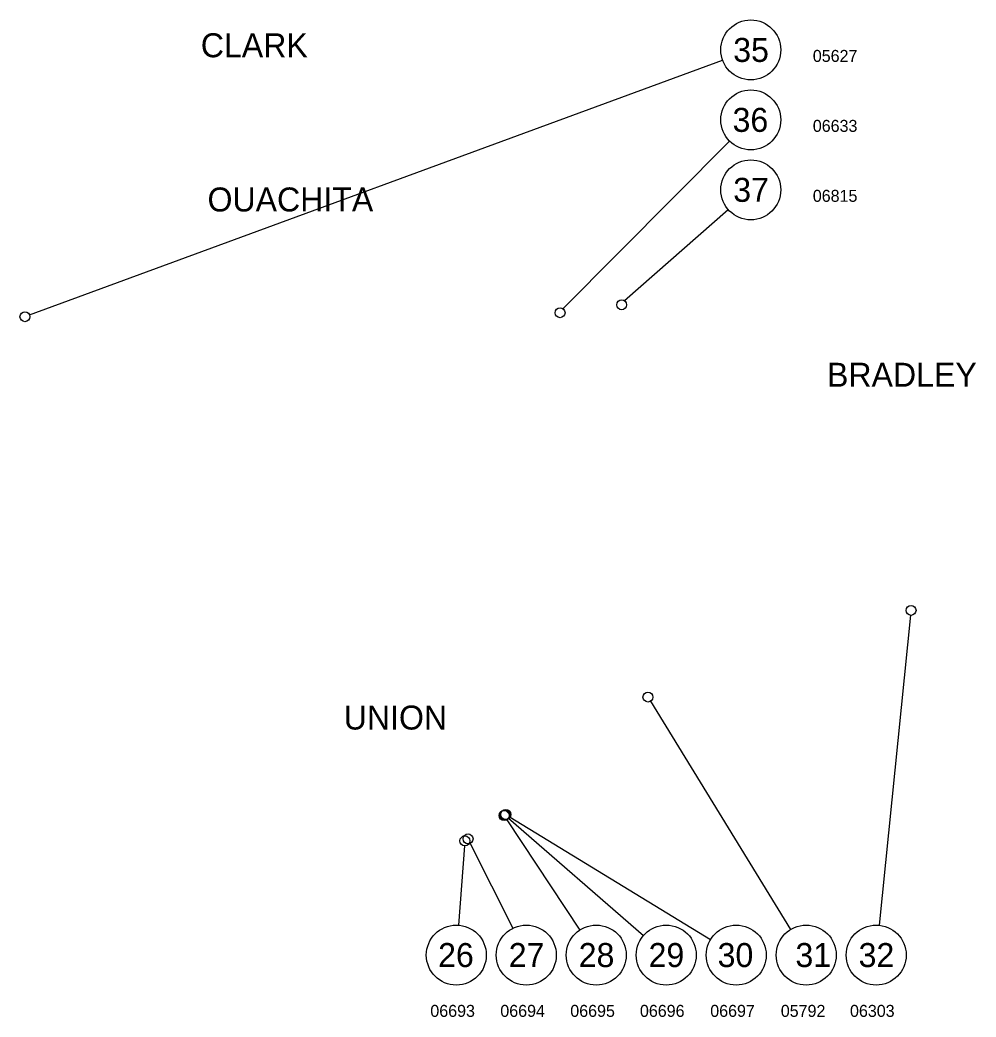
# Model space of a CAD drawing. Extents: x -43543 to 34500, y -13675 to 11152.
# Drawn here: x 24936 to 34500, y -7846 to 2131 of the extents above; entities that cross this region are included whole.
import ezdxf

# ---------------------------------------------------------------- set-up
doc = ezdxf.new("R2010")
doc.units = 0
for name, color, linetype in [('2', 7, 'Continuous'), ('R_Annotation', 7, 'Continuous'), ('R_No Plot', 7, 'Continuous')]:
    doc.layers.add(name, color=color, linetype=linetype)

msp = doc.modelspace()

# ---------------------------------------------------------------- linework, layer by layer
at = {"layer": 'R_Annotation'}
for p, q in [((25032.6, -820.5), (31965, 1728)), ((30367.8, -757.6), (32035, 918.8)), ((30983.5, -677.2), (32021.1, 233.6)), ((33844.7, -3825.8), (33531, -6926.7)), ((31244.4, -4686.3), (32644.1, -6969.5)), ((29806.6, -5871.5), (30535.5, -6974.9)), ((29824.3, -5857.1), (31174.3, -7028.6)), ((29838.3, -5845), (31844.7, -7069)), ((29382.9, -6133.1), (29323.3, -6926.1)), ((29440.3, -6107.4), (29866.4, -6957.1))]:
    msp.add_line(p, q, dxfattribs=at)
for centre, radius in [((32246.6, 1831.5), 300), ((32246.6, 1131.5), 300), ((32246.6, 431.5), 300), ((30954.9, -718.2), 50), ((24985.7, -837.8), 50), ((30338.4, -798.1), 50), ((33849.7, -3776), 50), ((31218.3, -4643.7), 50), ((29779.1, -5829.8), 50), ((29786.5, -5824.4), 50), ((29795.6, -5819), 50), ((29386.6, -6083.2), 50), ((29417.9, -6062.7), 50), ((29300.9, -7225.2), 300), ((30000.9, -7225.2), 300), ((30700.9, -7225.2), 300), ((31400.9, -7225.2), 300), ((32100.9, -7225.2), 300), ((32800.9, -7225.2), 300), ((33500.9, -7225.2), 300)]:
    msp.add_circle(centre, radius, dxfattribs=at)

# ---------------------------------------------------------------- texts
at = {"layer": '2'}
for s, p in [('CLARK', (26744.8, 1758.1)), ('OUACHITA', (26812, 215)), ('BRADLEY', (33008.8, -1538.7)), ('UNION', (28174.4, -4968.7))]:
    msp.add_text(s, height=240, dxfattribs=at).set_placement(p)
at = {"layer": 'R_Annotation'}
for s, p in [('35', (32070.8, 1711.5)), ('36', (32064.2, 1011.5)), ('37', (32070.8, 311.5)), ('26', (29118.5, -7345.2)), ('27', (29825.1, -7345.2)), ('28', (30525.1, -7345.2)), ('29', (31224.2, -7345.2)), ('30', (31914.7, -7345.2)), ('31', (32693.1, -7345.2)), ('32', (33325.1, -7345.2))]:
    msp.add_text(s, height=240, dxfattribs=at).set_placement(p)
at = {"layer": 'R_No Plot'}
for s, p in [('05627', (32867, 1711.5)), ('06633', (32867, 1011.5)), ('06815', (32867, 311.5)), ('06693', (29041, -7843.9)), ('06694', (29741, -7843.9)), ('06695', (30441, -7843.9)), ('06696', (31137.7, -7843.9)), ('06697', (31841, -7843.9)), ('05792', (32546.7, -7843.9)), ('06303', (33239.1, -7843.9))]:
    msp.add_text(s, height=120, dxfattribs=at).set_placement(p)

doc.saveas('drawing.dxf')
